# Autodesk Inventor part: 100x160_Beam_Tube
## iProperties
Shininess: 64.0
Length Units: 11269
Angle Units: 11279
Time Units: 11290
Mass Units: 11283
Length Display Precision: 3
Angle Display Precision: 2
Compacted: True
Part Number: 100x160_Beam_Tube
Document SubType Name: Modeling
Created: 2004-07
Designer: John Blackburn
Manufacturer: Standard
Standards Organization: Custom
Density: 0.0
Volumn: 0.0
Area: 0.0
PropertySet Name: Model Information
Control State: 0
Master: False
Checked Out: False
Author: John Blackburn
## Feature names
1. Extrusion1
